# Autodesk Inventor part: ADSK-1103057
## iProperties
Shininess: 20.0
Length Units: 11269
Angle Units: 11279
Time Units: 11290
Mass Units: 11283
Length Display Precision: 3
Angle Display Precision: 2
Created: 2001-06
Part Number: ADSK-1103057
Material: Steel, Mild
Document SubType Name: Modeling
Description: UHAN #3.873-ESX
Mass: 0.263888 g
Surface Area: 2.99213 cm^2
Volume: 0.0335735 cm^3
Density: 7.86 g/cm^3
Density: 7.86
Volumn: 3.5806394370622003
Area: 32.24046301072255
PropertySet Name: Model Information
Control State: 0
Master: False
Checked Out: False
msp_n: 18.000 ul
+MSCProtocol1+ProtocolID: P00060125011928546
+MSCProtocol2+Protocol: P00060125011928546<@PID>[Version]<@EL>Version=2.2<@EL>[Material]<@EL>MatID=<@EL>Material=User<@EL>Density=7850<@EL>[CalcData]<@EL>Scn1= 0<@EL>Scn2= 0<@EL>Scn3= 
Author: Autodesk, Inc.
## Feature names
1. Coil1
2. Revolution1
3. Sweep1
4. Sweep2
5. Revolution2
6. Sweep4
7. Sweep5
